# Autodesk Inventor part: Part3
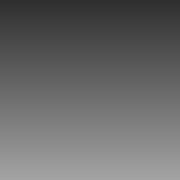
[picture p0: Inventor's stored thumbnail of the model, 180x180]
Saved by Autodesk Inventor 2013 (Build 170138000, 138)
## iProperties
Created: 2009-11
Part Number: Part3
Document SubType Name: Modeling
Designer: pokornp
Density: 1 g/cm^3
Material: Generic
Author: pokornp
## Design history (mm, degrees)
sketch "Sketch1"
  geometry: L1 (0, 0)-(2500, 0)
  constraints: 2 end point, 1 horizontal
  dimensions: "d0" = 2500 dimension on L1.start L1.end L1; "d0" = 2500 distance of L1.start L1.end
